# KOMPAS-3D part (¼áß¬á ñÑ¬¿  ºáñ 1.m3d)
File: created 06.04.2016 12:01:11, last saved 22.07.2016 15:58:26.
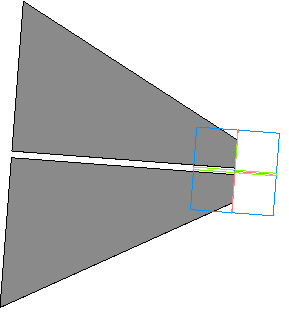
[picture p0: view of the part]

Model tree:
1. Эскиз:1
2. Операция выдавливания:1
     Толщина стенки 2 = 15; Расстояние 1 = 0.8; Расстояние 2 = 96.2519
3. Эскиз:2
4. Вырезать элемент выдавливания:1
     Толщина стенки 1 = 2; Толщина стенки 2 = 2; Расстояние 1 = 10
5. Эскиз:3
6. Вырезать элемент выдавливания:2
     Толщина стенки 1 = 2; Толщина стенки 2 = 2; Расстояние 1 = 10
7. Эскиз:4
8. Вырезать элемент выдавливания:3
     Толщина стенки 1 = 2; Толщина стенки 2 = 2; Расстояние 1 = 10.4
